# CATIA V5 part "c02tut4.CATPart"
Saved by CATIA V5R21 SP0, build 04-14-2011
Part number: c02tut4
Bounding box of the stored display mesh (mm): x 0 to 0, y -50 to 100, z -30 to 49.981
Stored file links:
  D:\CATIA V5R21 E-RESOURCES\CATIA-V5R21\catia-v5r21-prt\c02-catia-v5r21-prt\catia-v5r21-tut-4.CATPart
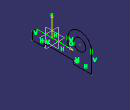
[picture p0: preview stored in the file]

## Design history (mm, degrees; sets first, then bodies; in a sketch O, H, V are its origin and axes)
Body1 (main body)
  Sketch1 on yz-plane, origin (0, 0, 0), H (0, 1, 0), V (0, 0, 1)
    line L1 (-50, -30) -> (-20, -30)
    line L2 (-20, -30) -> (-20, -22)
    line L3 (-20, -22) -> (55, -22)
    line L4 (55, -22) -> (55, -30)
    point P5 (55, -30)
    line L5 (55, -30) -> (100, -30)
    line L6 (100, -30) -> (100, 20)
    arc A1 centre (70, 20) radius 30 from (100, 20) to (40, 20) ccw
    line L7 (40, 20) -> (40, 0)
    point P10 (40, 0)
    line L8 (40, 0) -> (-40, 0)
    line L9 (-40, 0) -> (-50, -10)
    line L10 (-50, -10) -> (-50, -30)
    circle A2 centre (70, 20) radius 15
    length L2 = 8
    length L3 = 75
    horizontal: L1 H, L3 H, L5 H, L8 H
    vertical: L2 V, L4 V, L6 V, L10 V, L7 V
    coincidence: P5 L1, P10 H
    tangency: A1 L6, L7 A1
